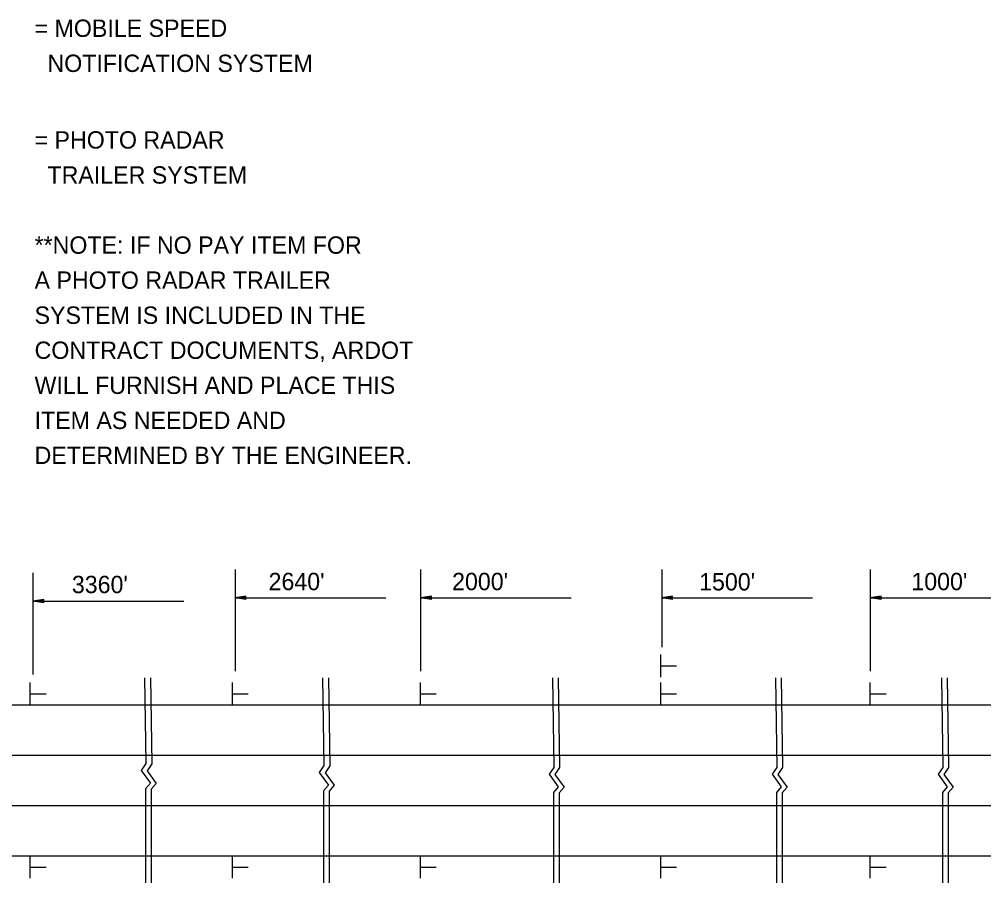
# Model space of a CAD drawing. Extents: x 1373848 to 1374003, y 380642 to 381248.
# Drawn here: x 1373881.84 to 1373915.22, y 381216.89 to 381246.77 of the extents above; entities that cross this region are included whole.
import ezdxf

# ---------------------------------------------------------------- set-up
doc = ezdxf.new("R2010")
doc.units = 0
doc.layers.add('Default', color=7, linetype='Continuous')

msp = doc.modelspace()

# ---------------------------------------------------------------- linework, layer by layer
at = {"layer": 'Default'}
for p, q in [((1373882.318, 381227.612), (1373882.318, 381224.091)), ((1373889.314, 381227.732), (1373889.314, 381224.211)), ((1373895.731, 381227.732), (1373895.731, 381224.211)), ((1373904.083, 381227.732), (1373904.083, 381225.047)), ((1373911.3, 381227.732), (1373911.3, 381224.211)), ((1373882.693, 381226.689), (1373882.318, 381226.633)), ((1373882.318, 381226.633), (1373887.537, 381226.633)), ((1373882.693, 381226.577), (1373882.318, 381226.633)), ((1373882.693, 381226.68), (1373882.381, 381226.633)), ((1373882.693, 381226.586), (1373882.381, 381226.633)), ((1373882.693, 381226.67), (1373882.445, 381226.633)), ((1373882.693, 381226.596), (1373882.445, 381226.633)), ((1373882.693, 381226.661), (1373882.507, 381226.633)), ((1373882.693, 381226.605), (1373882.507, 381226.633)), ((1373882.693, 381226.651), (1373882.571, 381226.633)), ((1373882.693, 381226.615), (1373882.571, 381226.633)), ((1373882.693, 381226.642), (1373882.634, 381226.633)), ((1373882.693, 381226.624), (1373882.634, 381226.633)), ((1373882.693, 381226.577), (1373882.693, 381226.689)), ((1373889.689, 381226.809), (1373889.314, 381226.753)), ((1373889.314, 381226.753), (1373894.533, 381226.753)), ((1373889.689, 381226.697), (1373889.314, 381226.753)), ((1373889.689, 381226.8), (1373889.377, 381226.753)), ((1373889.689, 381226.706), (1373889.377, 381226.753)), ((1373889.689, 381226.79), (1373889.442, 381226.753)), ((1373889.689, 381226.716), (1373889.442, 381226.753)), ((1373889.689, 381226.781), (1373889.504, 381226.753)), ((1373889.689, 381226.725), (1373889.504, 381226.753)), ((1373889.689, 381226.771), (1373889.568, 381226.753)), ((1373889.689, 381226.735), (1373889.568, 381226.753)), ((1373889.689, 381226.762), (1373889.63, 381226.753)), ((1373889.689, 381226.744), (1373889.63, 381226.753)), ((1373889.689, 381226.697), (1373889.689, 381226.809)), ((1373896.106, 381226.809), (1373895.731, 381226.753)), ((1373895.731, 381226.753), (1373900.949, 381226.753)), ((1373896.106, 381226.697), (1373895.731, 381226.753)), ((1373896.106, 381226.8), (1373895.793, 381226.753)), ((1373896.106, 381226.706), (1373895.793, 381226.753)), ((1373896.106, 381226.79), (1373895.858, 381226.753)), ((1373896.106, 381226.716), (1373895.858, 381226.753)), ((1373896.106, 381226.781), (1373895.92, 381226.753)), ((1373896.106, 381226.725), (1373895.92, 381226.753)), ((1373896.106, 381226.771), (1373895.984, 381226.753)), ((1373896.106, 381226.735), (1373895.984, 381226.753)), ((1373896.106, 381226.762), (1373896.046, 381226.753)), ((1373896.106, 381226.744), (1373896.046, 381226.753)), ((1373896.106, 381226.697), (1373896.106, 381226.809)), ((1373904.458, 381226.809), (1373904.083, 381226.753)), ((1373904.083, 381226.753), (1373909.302, 381226.753)), ((1373904.458, 381226.697), (1373904.083, 381226.753)), ((1373904.458, 381226.8), (1373904.146, 381226.753)), ((1373904.458, 381226.706), (1373904.146, 381226.753)), ((1373904.458, 381226.79), (1373904.21, 381226.753)), ((1373904.458, 381226.716), (1373904.21, 381226.753)), ((1373904.458, 381226.781), (1373904.273, 381226.753)), ((1373904.458, 381226.725), (1373904.273, 381226.753)), ((1373904.458, 381226.771), (1373904.336, 381226.753)), ((1373904.458, 381226.735), (1373904.336, 381226.753)), ((1373904.458, 381226.762), (1373904.399, 381226.753)), ((1373904.458, 381226.744), (1373904.399, 381226.753)), ((1373904.458, 381226.697), (1373904.458, 381226.809)), ((1373911.675, 381226.809), (1373911.3, 381226.753)), ((1373911.3, 381226.753), (1373916.518, 381226.753)), ((1373911.675, 381226.697), (1373911.3, 381226.753)), ((1373911.675, 381226.8), (1373911.362, 381226.753)), ((1373911.675, 381226.706), (1373911.362, 381226.753)), ((1373911.675, 381226.79), (1373911.427, 381226.753)), ((1373911.675, 381226.716), (1373911.427, 381226.753)), ((1373911.675, 381226.781), (1373911.489, 381226.753)), ((1373911.675, 381226.725), (1373911.489, 381226.753)), ((1373911.675, 381226.771), (1373911.553, 381226.753)), ((1373911.675, 381226.735), (1373911.553, 381226.753)), ((1373911.675, 381226.762), (1373911.615, 381226.753)), ((1373911.675, 381226.744), (1373911.615, 381226.753)), ((1373911.675, 381226.697), (1373911.675, 381226.809)), ((1373904.047, 381224.007), (1373904.047, 381224.789)), ((1373904.058, 381224.396), (1373904.592, 381224.396)), ((1373882.227, 381223.041), (1373882.227, 381223.824)), ((1373889.223, 381223.041), (1373889.223, 381223.824)), ((1373895.731, 381223.041), (1373895.731, 381223.824)), ((1373904.045, 381223.041), (1373904.045, 381223.824)), ((1373911.3, 381223.041), (1373911.3, 381223.824)), ((1373882.238, 381223.43), (1373882.772, 381223.43)), ((1373889.235, 381223.43), (1373889.769, 381223.43)), ((1373895.742, 381223.43), (1373896.276, 381223.43)), ((1373904.056, 381223.43), (1373904.59, 381223.43)), ((1373911.311, 381223.43), (1373911.845, 381223.43)), ((1373854.616, 381223.041), (1373996.342, 381223.041)), ((1373854.616, 381221.303), (1373996.342, 381221.303)), ((1373854.616, 381219.564), (1373996.342, 381219.564)), ((1373854.616, 381217.826), (1373996.342, 381217.826)), ((1373882.227, 381217.043), (1373882.227, 381217.826)), ((1373889.223, 381217.043), (1373889.223, 381217.826)), ((1373895.731, 381217.043), (1373895.731, 381217.826)), ((1373904.045, 381217.043), (1373904.045, 381217.826)), ((1373911.3, 381217.043), (1373911.3, 381217.826)), ((1373882.238, 381217.432), (1373882.772, 381217.432)), ((1373889.235, 381217.432), (1373889.769, 381217.432)), ((1373895.742, 381217.432), (1373896.276, 381217.432)), ((1373904.056, 381217.432), (1373904.59, 381217.432)), ((1373911.311, 381217.432), (1373911.845, 381217.432))]:
    msp.add_line(p, q, dxfattribs=at)
for points in [[(1373886.182, 381223.977), (1373886.227, 381221.011), (1373886.065, 381220.77), (1373886.381, 381220.337), (1373886.215, 381220.137), (1373886.214, 381216.89)], [(1373886.382, 381223.977), (1373886.427, 381221.003), (1373886.265, 381220.761), (1373886.581, 381220.329), (1373886.414, 381220.129), (1373886.414, 381216.89)], [(1373892.342, 381223.977), (1373892.388, 381220.946), (1373892.226, 381220.704), (1373892.542, 381220.271), (1373892.376, 381220.071), (1373892.375, 381216.89)], [(1373892.542, 381223.977), (1373892.588, 381220.937), (1373892.426, 381220.696), (1373892.742, 381220.263), (1373892.575, 381220.063), (1373892.575, 381216.89)], [(1373900.298, 381223.977), (1373900.345, 381220.883), (1373900.182, 381220.641), (1373900.499, 381220.208), (1373900.332, 381220.008), (1373900.331, 381216.89)], [(1373900.497, 381223.977), (1373900.544, 381220.874), (1373900.382, 381220.633), (1373900.698, 381220.2), (1373900.532, 381220), (1373900.531, 381216.89)], [(1373908.015, 381223.977), (1373908.062, 381220.883), (1373907.9, 381220.641), (1373908.216, 381220.208), (1373908.05, 381220.008), (1373908.049, 381216.89)], [(1373908.215, 381223.977), (1373908.262, 381220.874), (1373908.1, 381220.633), (1373908.416, 381220.2), (1373908.25, 381220), (1373908.249, 381216.89)], [(1373913.761, 381223.977), (1373913.808, 381220.883), (1373913.646, 381220.641), (1373913.962, 381220.208), (1373913.796, 381220.008), (1373913.795, 381216.89)], [(1373913.961, 381223.977), (1373914.008, 381220.874), (1373913.846, 381220.633), (1373914.162, 381220.2), (1373913.996, 381220), (1373913.995, 381216.89)]]:
    msp.add_lwpolyline(points, dxfattribs=at)

# ---------------------------------------------------------------- texts
for s, p in [('= MOBILE SPEED', (1373882.374, 381246.161)), ('  NOTIFICATION SYSTEM', (1373882.374, 381244.948)), ('= PHOTO RADAR', (1373882.374, 381242.296)), ('  TRAILER SYSTEM', (1373882.374, 381241.083)), ('**NOTE: IF NO PAY ITEM FOR', (1373882.374, 381238.657)), ('A PHOTO RADAR TRAILER', (1373882.374, 381237.444)), ('SYSTEM IS INCLUDED IN THE', (1373882.374, 381236.231)), ('CONTRACT DOCUMENTS, ARDOT', (1373882.374, 381235.018)), ('WILL FURNISH AND PLACE THIS', (1373882.374, 381233.805)), ('ITEM AS NEEDED AND', (1373882.374, 381232.592)), ('DETERMINED BY THE ENGINEER.', (1373882.374, 381231.379)), ("3360'", (1373883.664, 381226.911)), ("2640'", (1373890.472, 381227.014)), ("2000'", (1373896.824, 381227.014)), ("1500'", (1373905.374, 381227.005)), ("1000'", (1373912.72, 381227.014))]:
    msp.add_text(s, height=0.6, dxfattribs=at).set_placement(p)

doc.saveas('drawing.dxf')
